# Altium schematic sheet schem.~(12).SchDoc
size A; SheetNumber: 1; SheetTotal: 1
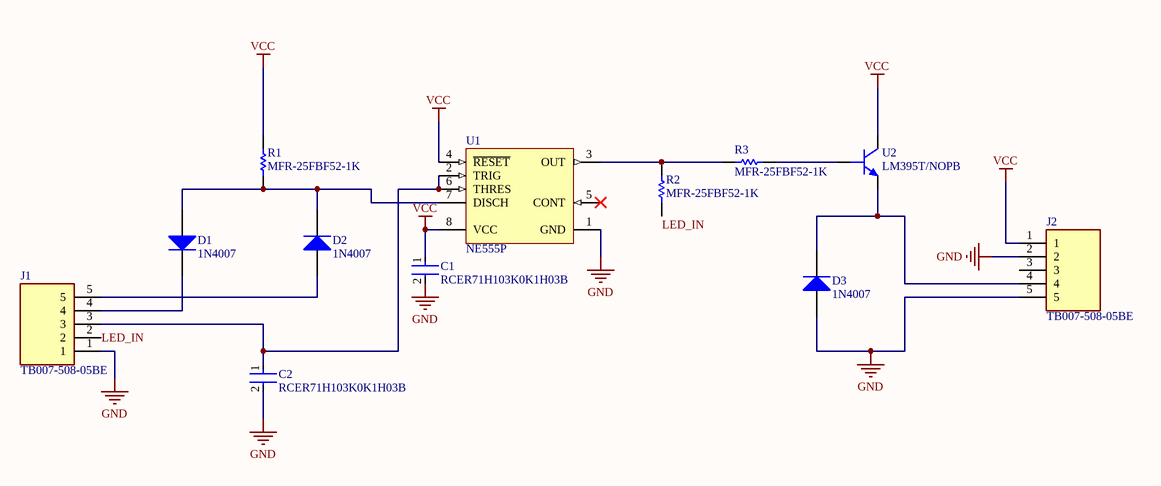
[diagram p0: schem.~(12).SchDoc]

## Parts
C1  RCER71H103K0K1H03B  [FP-RCE0K1-MFG]
C2  RCER71H103K0K1H03B  [FP-RCE0K1-MFG]
D1  1N4007  [FAIR-DO-41-2]
D2  1N4007  [FAIR-DO-41-2]
D3  1N4007  [FAIR-DO-41-2]
J1  TB007-508-05BE  [CUI_TB007-508-05BE]
J2  TB007-508-05BE  [CUI_TB007-508-05BE]
R1  MFR-25FBF52-1K  [RESA60-630X240]
R2  MFR-25FBF52-1K  [RESA60-630X240]
R3  MFR-25FBF52-1K  [RESA60-630X240]
U1  NE555P  [P0008A]
U2  LM395T/NOPB  [NDE0003A]

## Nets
GND: C1.2 C2.2 D3.2(A) J1.1 J2.2 J2.5 U1.1(GND)
VCC: C1.1 J2.1 R1.2 U1.4(~{RESET}) U1.8(VCC) U2.3(C)
LED_IN: J1.2 R2.1
NetC2_1: C2.1 J1.3 U1.2(TRIG) U1.6(THRES)
NetD1_1: D1.1(K) J1.4
NetD1_2: D1.2(A) D2.1(K) R1.1 U1.7(DISCH)
NetD2_2: D2.2(A) J1.5
NetD3_1: D3.1(K) J2.4 U2.2(E)
NetR2_2: R2.2 R3.2 U1.3(OUT)
NetR3_1: R3.1 U2.1(B)

Not connected (* = marked no-connect by the designer): J2 3; U1 5(CONT)*

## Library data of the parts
C1 C2 = CMP-06035-044411-1: Cap Ceramic 10nF 50V X7R ±10% Radial 5mm +125°C Automotive Bulk; Lead/Base Style: Formed Leads; Lead Diameter: 0.5mm
D1-D3 = CMP-004-00007-1: General Purpose Rectifier, 1.1 V, 1.0 A, -55 to 175 degC, 2-Pin DO-41, RoHS, Tape and Reel; Manufacturer: Fairchild; Package Version: Rev. 2, 09/2008; Elements: 1; Forward Current: 1A; Max Surge Current: 30A; Forward Voltage: 1.1V; Peak Reverse Current: 5uA
R1-R3 = CMP-1659-00075-1: Axial Resistor, 1 KOhm, +/- 1%, 250 mW, -55 to 155 degC, 2-Pin THD, RoHS, Bulk; Voltage Rating: 250 V; Resistance: 10 kohm; Power Rating: 250 mW
U1 = CMP-2000-04954-1: Precision Timer, 4.5 to 16 V, 0 to 70 degC, 8-Pin DIP, Pb-Free, Tube; Manufacturer: TexasInstruments; Maximum High Level Output Current: -200mA; Number of Internal Timers: 1; Operating Supply Voltage: 5; Maximum Low Level Output Current: 200mA; Rad Hard: No
U2 = CMP-0063-01416-3: Ultra Reliable Power Transistor, 3-pin TO-220, Pb-Free; Manufacturer: Texas Instruments; PowerWise: N; PackageTopMarking: NSUZXYTTE#*LM395T; CompType: MiscPower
